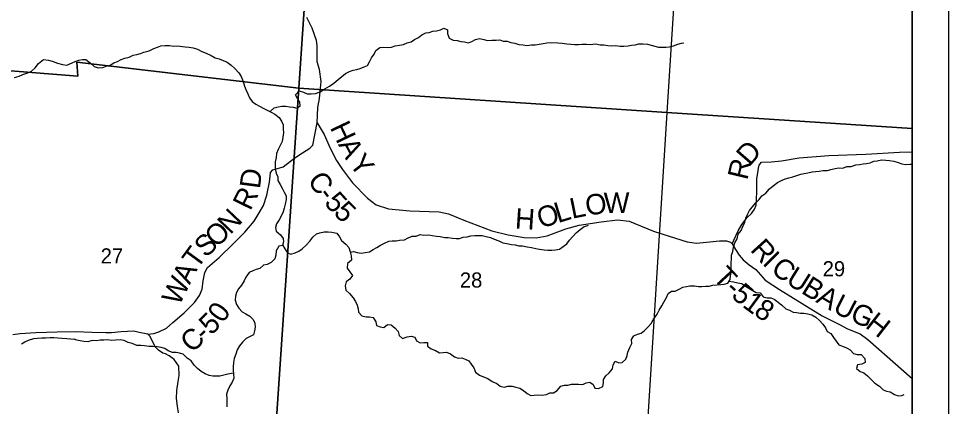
# Model space of a CAD drawing. Extents: x 0 to 34, y 0 to 22.
# Drawn here: x 28.342 to 30.917, y 17.138 to 18.211 of the extents above; entities that cross this region are included whole.
import ezdxf

# ---------------------------------------------------------------- set-up
doc = ezdxf.new("R2010")
doc.units = 0
for name, color, linetype in [('GM_X_County', 7, 'Continuous'), ('GM_X_County_Road', 7, 'Continuous'), ('GM_X_County_Road_Text', 7, 'Continuous'), ('GM_X_Minor_River', 7, 'Continuous'), ('GM_X_Section', 7, 'Continuous'), ('GM_X_Section_Text', 7, 'Continuous'), ('GM_X_State_Route', 7, 'Continuous'), ('GM_X_Township', 7, 'Continuous'), ('GM_X_Township_Road', 7, 'Continuous'), ('GM_X_Township_Road_Text', 7, 'Continuous'), ('SH_Data', 7, 'Continuous')]:
    doc.layers.add(name, color=color, linetype=linetype)

msp = doc.modelspace()

# ---------------------------------------------------------------- linework, layer by layer
at = {"layer": 'GM_X_County'}
msp.add_lwpolyline([(24.0167, 20.4902), (24.0167, 14.1), (30.8167, 14.1), (30.8167, 19.9966)], dxfattribs=at)
at = {"layer": 'GM_X_County_Road'}
for points in [[(29.1692, 17.9224), (29.1692, 17.9224), (29.1706, 17.9649), (29.1749, 17.9903), (29.1769, 18.0097), (29.1794, 18.0373), (29.1754, 18.07), (29.1691, 18.0917), (29.1692, 18.1065), (29.1686, 18.1368), (29.1671, 18.1501), (29.1552, 18.1847), (29.1406, 18.2141)], [(28.7, 17.3377), (28.7168, 17.3398), (28.7304, 17.3439), (28.7519, 17.354), (28.7694, 17.3695), (28.8003, 17.397), (28.8288, 17.4249), (28.8433, 17.4446), (28.8499, 17.462), (28.8527, 17.4847), (28.8581, 17.5082), (28.865, 17.5219), (28.8974, 17.5501), (28.9366, 17.5875), (28.9686, 17.6196), (28.9942, 17.6505), (29.0083, 17.6732), (29.0198, 17.6933), (29.029, 17.7224), (29.0364, 17.7581), (29.0384, 17.7748), (29.0393, 17.7854), (29.0461, 17.7922), (29.0526, 17.794), (29.0655, 17.7978), (29.0746, 17.8004), (29.1073, 17.8252), (29.1278, 17.8399), (29.1487, 17.8527), (29.1567, 17.861), (29.1692, 17.9224)], [(29.1692, 17.9224), (29.1884, 17.8904), (29.2052, 17.852), (29.2224, 17.8185), (29.2385, 17.7933), (29.2663, 17.7567), (29.3085, 17.714), (29.3323, 17.6953), (29.3667, 17.6848), (29.4257, 17.6792), (29.4787, 17.677), (29.5064, 17.6757), (29.5325, 17.6706), (29.5752, 17.6532), (29.6527, 17.624), (29.6981, 17.6123), (29.7419, 17.6052), (29.7756, 17.6043), (29.806, 17.6098), (29.8572, 17.6292), (29.8944, 17.6389), (29.9554, 17.6488), (30.0005, 17.6542), (30.0331, 17.6506), (30.1004, 17.6225), (30.1431, 17.609), (30.193, 17.5935), (30.2191, 17.5892), (30.2562, 17.5931), (30.2831, 17.596), (30.3025, 17.5959), (30.313, 17.5923), (30.3176, 17.5875)], [(30.3176, 17.5875), (30.3225, 17.5973), (30.3344, 17.6234), (30.3451, 17.6412), (30.3596, 17.6605), (30.3711, 17.6718), (30.3802, 17.6835), (30.3841, 17.6949), (30.3857, 17.7131), (30.3862, 17.7294), (30.3863, 17.7438), (30.3864, 17.7681), (30.3888, 17.7844), (30.3908, 17.7973), (30.3931, 17.8053), (30.3992, 17.814), (30.4268, 17.8146), (30.4545, 17.8171), (30.5034, 17.8259), (30.5856, 17.8319), (30.6876, 17.8359), (30.7808, 17.8414), (30.8167, 17.8418)]]:
    msp.add_lwpolyline(points, dxfattribs=at)
at = {"layer": 'GM_X_Minor_River'}
for points in [[(29.0384, 17.9535), (29.0497, 17.9641), (29.0611, 17.9668), (29.0706, 17.9685), (29.082, 17.969), (29.0918, 17.9665), (29.102, 17.9656), (29.1122, 17.9634), (29.1218, 17.9697), (29.1205, 17.9799), (29.1139, 17.9903), (29.1092, 17.9999), (29.1189, 18.0111), (29.1313, 18.007), (29.1415, 18.003), (29.1521, 18.0028), (29.1638, 18.0036), (29.1772, 18.0086), (29.1902, 18.0163), (29.2025, 18.0244), (29.2145, 18.0325), (29.2272, 18.0424), (29.2372, 18.0509), (29.2469, 18.0587), (29.258, 18.0645), (29.2687, 18.0681), (29.2782, 18.0705), (29.2877, 18.0726), (29.2988, 18.0776), (29.3083, 18.0816), (29.3135, 18.0913), (29.3194, 18.1026), (29.3268, 18.1123), (29.3312, 18.1228), (29.342, 18.1313), (29.3534, 18.1322), (29.3651, 18.1311), (29.3746, 18.1321), (29.3849, 18.1356), (29.3963, 18.1373), (29.4077, 18.1393), (29.4181, 18.1436), (29.4287, 18.1472), (29.4383, 18.1534), (29.4491, 18.1589), (29.4587, 18.1659), (29.4694, 18.1713), (29.4789, 18.173), (29.4889, 18.1766), (29.4991, 18.1775), (29.5101, 18.1803), (29.5197, 18.1842), (29.5295, 18.1798), (29.5296, 18.1696), (29.5346, 18.1573), (29.5451, 18.1514), (29.5564, 18.1504), (29.567, 18.1479), (29.5768, 18.1465), (29.5877, 18.1444), (29.5973, 18.1476), (29.6073, 18.1531), (29.6187, 18.1559), (29.6304, 18.1533), (29.6405, 18.1508), (29.6527, 18.1513), (29.664, 18.1518), (29.6743, 18.1523), (29.684, 18.1487), (29.695, 18.1485), (29.7052, 18.1448), (29.7161, 18.1431), (29.727, 18.139), (29.7395, 18.1384), (29.7493, 18.137), (29.7618, 18.1383), (29.772, 18.138), (29.7835, 18.1404), (29.7949, 18.1421), (29.8044, 18.1441), (29.8146, 18.1447), (29.8351, 18.1442), (29.8471, 18.1428), (29.8604, 18.141), (29.8713, 18.14), (29.8815, 18.139), (29.8921, 18.1395), (29.9024, 18.1405), (29.9145, 18.1402), (29.9247, 18.1392), (29.9391, 18.1415), (29.9523, 18.1386), (29.9629, 18.1383), (29.9739, 18.137), (29.9837, 18.136), (29.9951, 18.1365), (30.0075, 18.1347), (30.0178, 18.1352), (30.0295, 18.1361), (30.039, 18.1374), (30.0489, 18.1387)], [(28.4989, 18.0924), (28.5092, 18.0956), (28.5187, 18.0976), (28.5285, 18.0974), (28.5404, 18.0884), (28.5516, 18.0787), (28.5621, 18.075), (28.575, 18.0759), (28.5849, 18.0791), (28.5952, 18.0819), (28.606, 18.0885), (28.6155, 18.0924), (28.6262, 18.0983), (28.6365, 18.1011), (28.6484, 18.1042), (28.6591, 18.11), (28.6693, 18.1113), (28.6796, 18.1149), (28.6892, 18.1181), (28.7033, 18.1223), (28.7167, 18.1285), (28.7266, 18.1317), (28.7362, 18.1353), (28.7483, 18.1369), (28.7597, 18.1363), (28.7721, 18.1345), (28.782, 18.1354), (28.8031, 18.1326), (28.8148, 18.1316), (28.8254, 18.1299), (28.8371, 18.1266), (28.8498, 18.1202), (28.8611, 18.1154), (28.8749, 18.1087), (28.8862, 18.1027), (28.8971, 18.0998), (28.9087, 18.0954), (28.9192, 18.0906), (28.9304, 18.082), (28.9404, 18.0731), (28.9515, 18.0614), (28.9581, 18.0511), (28.9635, 18.0373), (28.9677, 18.0243), (28.9713, 18.0144), (28.9771, 18.0025), (28.981, 17.9921), (28.9887, 17.9813), (28.9988, 17.9739), (29.0089, 17.9691), (29.0209, 17.962), (29.0306, 17.9577), (29.0411, 17.9521), (29.0516, 17.9462), (29.0631, 17.9376), (29.0697, 17.9268), (29.0748, 17.9172), (29.0745, 17.9062), (29.0754, 17.8952), (29.0736, 17.8827), (29.0715, 17.8707), (29.0667, 17.8601), (29.0607, 17.8489), (29.0559, 17.8372), (29.0557, 17.8266), (29.0528, 17.8149), (29.0529, 17.8051), (29.0527, 17.7956), (29.0555, 17.783), (29.0594, 17.7734), (29.0596, 17.7628), (29.0662, 17.7521), (29.0731, 17.7401), (29.0774, 17.7302), (29.0825, 17.7202), (29.083, 17.71), (29.0805, 17.6975), (29.0776, 17.6862), (29.0747, 17.676), (29.0691, 17.6644), (29.0632, 17.6539), (29.0561, 17.6427), (29.0536, 17.6329), (29.0557, 17.623), (29.0668, 17.6121), (29.0749, 17.6024), (29.0751, 17.5929), (29.0726, 17.5831), (29.0627, 17.5807), (29.0556, 17.568), (29.0546, 17.5566), (29.0517, 17.546), (29.0416, 17.536), (29.0305, 17.5302), (29.0199, 17.5285), (29.0102, 17.5189), (28.9999, 17.5165), (28.9904, 17.5129), (28.9808, 17.5082), (28.971, 17.4951), (28.9662, 17.485)], [(30.0489, 18.1387), (30.0596, 18.1415), (30.0709, 18.1416), (30.0834, 18.1402), (30.0932, 18.1374), (30.1037, 18.1348), (30.1135, 18.132), (30.1237, 18.1317), (30.134, 18.1319), (30.1438, 18.1328), (30.1553, 18.1356), (30.1671, 18.1403), (30.1778, 18.1431), (30.1842, 18.1444)], [(28.331, 18.0478), (28.3432, 18.0514), (28.3539, 18.0562), (28.3676, 18.061), (28.3779, 18.0655), (28.3878, 18.0748), (28.3974, 18.0872), (28.4108, 18.0981), (28.4248, 18.0964), (28.4354, 18.0936), (28.4501, 18.0881), (28.4633, 18.0842), (28.4754, 18.0822), (28.4989, 18.0924)], [(30.6998, 17.8117), (30.7101, 17.8161), (30.7196, 17.8174), (30.7311, 17.8198), (30.7436, 17.8195), (30.7537, 17.8181), (30.7654, 17.816), (30.7771, 17.8123), (30.7876, 17.8086), (30.7982, 17.8073), (30.8096, 17.8078), (30.8167, 17.8082)], [(29.904, 17.1986), (29.9136, 17.2026), (29.9235, 17.2047), (29.9332, 17.198), (29.9379, 17.188), (29.9477, 17.1871), (29.9596, 17.1929), (29.962, 17.2027), (29.9619, 17.2121), (29.9678, 17.2219), (29.9774, 17.2304), (29.9864, 17.2412), (29.9885, 17.2525), (29.9941, 17.263), (30.0038, 17.2586), (30.0137, 17.2592), (30.0237, 17.268), (30.0274, 17.2782), (30.0291, 17.288), (30.0347, 17.3008), (30.0402, 17.3117), (30.039, 17.3223), (30.046, 17.3332), (30.056, 17.3379), (30.0655, 17.3399), (30.0751, 17.3473), (30.0848, 17.357), (30.0934, 17.367), (30.0993, 17.3771), (30.1098, 17.3928), (30.1162, 17.4044), (30.1232, 17.4157), (30.1284, 17.4262), (30.1359, 17.4389), (30.1403, 17.4502), (30.1503, 17.4564), (30.1597, 17.4566), (30.1716, 17.462), (30.1816, 17.4675), (30.1911, 17.4699), (30.2006, 17.4716), (30.2135, 17.4717), (30.2244, 17.4695), (30.2343, 17.4693), (30.2449, 17.4702), (30.2544, 17.4708), (30.2647, 17.4736), (30.276, 17.4741), (30.2863, 17.4754), (30.2958, 17.4763), (30.3057, 17.4787), (30.312, 17.4885), (30.3129, 17.4987), (30.3154, 17.5089), (30.315, 17.5221), (30.3149, 17.5347), (30.3159, 17.546), (30.3165, 17.5559), (30.3194, 17.5668), (30.3219, 17.5781), (30.3252, 17.5906), (30.3319, 17.6014), (30.3349, 17.6146), (30.343, 17.6247), (30.3478, 17.6356), (30.353, 17.6476), (30.3559, 17.6589), (30.3603, 17.6687), (30.3658, 17.6796), (30.3733, 17.6893), (30.3834, 17.7008), (30.393, 17.7101), (30.4001, 17.7201), (30.4113, 17.7282), (30.4213, 17.7394), (30.4318, 17.7483), (30.443, 17.7575), (30.4548, 17.7625), (30.4644, 17.7673), (30.4747, 17.7701), (30.4861, 17.7732), (30.4968, 17.7768), (30.5079, 17.7807), (30.5177, 17.782), (30.5273, 17.7841), (30.5391, 17.7869), (30.5493, 17.7874), (30.5588, 17.7883), (30.5694, 17.7907), (30.5816, 17.7908), (30.5915, 17.7933), (30.6029, 17.7964), (30.6135, 17.7977), (30.6241, 17.7975), (30.6356, 17.8018), (30.647, 17.8015), (30.6599, 17.8065), (30.6702, 17.8075), (30.6804, 17.8087), (30.6903, 17.8104), (30.6998, 17.8117)], [(29.2599, 17.5645), (29.2695, 17.5659), (29.2797, 17.5637), (29.2903, 17.562), (29.302, 17.5632), (29.3134, 17.5653), (29.3238, 17.5719), (29.3342, 17.5777), (29.3442, 17.5835), (29.3556, 17.5894), (29.3668, 17.5948), (29.3762, 17.5961), (29.3876, 17.5959), (29.3971, 17.5979), (29.4104, 17.5988), (29.4211, 17.6038), (29.4314, 17.6085), (29.4428, 17.609), (29.4543, 17.613), (29.4641, 17.6112), (29.477, 17.6121), (29.4868, 17.6103), (29.4992, 17.6085), (29.5098, 17.6079), (29.5219, 17.605), (29.5317, 17.6048), (29.5438, 17.603), (29.5536, 17.6024), (29.5631, 17.6026), (29.5726, 17.6058), (29.5844, 17.6066), (29.5947, 17.6098), (29.6057, 17.6111), (29.6156, 17.6105), (29.6258, 17.6103), (29.6371, 17.6081), (29.6491, 17.6048), (29.6589, 17.6001), (29.6716, 17.5956), (29.6833, 17.5904), (29.6935, 17.5883), (29.707, 17.5857), (29.7172, 17.5844), (29.7274, 17.5822), (29.7372, 17.582), (29.7504, 17.5794), (29.7618, 17.5777), (29.7742, 17.5751), (29.7848, 17.573), (29.7972, 17.5712), (29.8074, 17.5698), (29.8184, 17.57), (29.8283, 17.5709), (29.8401, 17.5729), (29.8504, 17.5803), (29.8601, 17.5873), (29.8675, 17.5977), (29.8768, 17.6081), (29.8858, 17.6182), (29.8969, 17.627), (29.9081, 17.6355), (29.9184, 17.6387), (29.9199, 17.6394)], [(29.073, 17.5846), (29.0788, 17.5735), (29.0862, 17.5631), (29.0959, 17.5587), (29.1074, 17.5623), (29.1177, 17.5677), (29.1273, 17.5736), (29.1385, 17.5843), (29.1482, 17.5947), (29.1568, 17.6059), (29.1669, 17.6152), (29.1764, 17.6184), (29.1878, 17.6208), (29.1996, 17.6205), (29.2098, 17.6199), (29.2233, 17.6169), (29.2307, 17.6065), (29.2365, 17.5969), (29.2477, 17.5868), (29.2565, 17.5771), (29.2597, 17.5653), (29.2628, 17.5539), (29.2637, 17.5428), (29.2525, 17.5329), (29.2518, 17.5204), (29.2592, 17.51), (29.2669, 17.5003), (29.2591, 17.4902), (29.2495, 17.4825), (29.2466, 17.4715), (29.2486, 17.459), (29.2582, 17.45), (29.2686, 17.4384), (29.2751, 17.4277), (29.2795, 17.4181), (29.2819, 17.4078), (29.2836, 17.3983), (29.2924, 17.3882), (29.3041, 17.3857), (29.314, 17.3858), (29.3242, 17.3837), (29.3311, 17.3718), (29.3331, 17.3619), (29.3436, 17.3575), (29.3534, 17.3558), (29.3635, 17.3643), (29.3741, 17.3633), (29.3845, 17.3543), (29.3926, 17.3447), (29.3954, 17.334), (29.405, 17.3254), (29.4176, 17.3297), (29.429, 17.3317), (29.4392, 17.3288), (29.4435, 17.3189), (29.4544, 17.3133), (29.4642, 17.3142), (29.4741, 17.3148), (29.4746, 17.3045), (29.4847, 17.2967), (29.4967, 17.2923), (29.5075, 17.286), (29.5174, 17.2865), (29.5273, 17.2878), (29.5382, 17.2834), (29.549, 17.2752), (29.5591, 17.2715), (29.569, 17.2721), (29.5787, 17.2681), (29.5885, 17.2637), (29.5951, 17.2541), (29.6028, 17.2444), (29.6075, 17.2325), (29.6183, 17.2243), (29.6291, 17.2195), (29.6415, 17.2147), (29.6535, 17.2061), (29.6662, 17.2005), (29.6759, 17.1935), (29.6864, 17.191), (29.6963, 17.1934), (29.7088, 17.1931), (29.719, 17.191), (29.7295, 17.1877), (29.74, 17.1818), (29.75, 17.1729), (29.7602, 17.1677), (29.77, 17.169), (29.781, 17.1695), (29.792, 17.1685), (29.8034, 17.1705), (29.8133, 17.1749), (29.8232, 17.175), (29.8336, 17.182), (29.8433, 17.1932), (29.8532, 17.1967), (29.8631, 17.1965), (29.8726, 17.1993), (29.8824, 17.1987), (29.8923, 17.1989), (29.904, 17.1986)], [(28.9662, 17.485), (28.9595, 17.4734), (28.9514, 17.4629), (28.9451, 17.4532), (28.9422, 17.4427), (28.942, 17.4317), (28.9455, 17.4198), (28.9521, 17.4098), (28.9609, 17.3994), (28.971, 17.3938), (28.9822, 17.3871), (28.9919, 17.3778), (28.9958, 17.3683), (28.9975, 17.3572), (28.9954, 17.347), (28.9924, 17.3357), (28.9817, 17.3303), (28.9721, 17.3255), (28.9621, 17.3155), (28.9539, 17.3051), (28.9472, 17.2946), (28.9435, 17.2818), (28.9387, 17.2698), (28.9373, 17.2588), (28.9359, 17.2475), (28.9361, 17.2376), (28.9374, 17.2266), (28.9382, 17.2156), (28.9331, 17.2043), (28.9268, 17.1942), (28.9216, 17.1825), (28.9176, 17.1713), (28.9188, 17.1595), (28.919, 17.1492), (28.9183, 17.1367)], [(30.3093, 17.4843), (30.3213, 17.4826), (30.3334, 17.48), (30.3447, 17.4775), (30.3547, 17.4701), (30.3644, 17.4645), (30.3749, 17.4586), (30.3846, 17.4531), (30.3956, 17.4517), (30.404, 17.4405), (30.415, 17.4384), (30.4248, 17.4382), (30.4346, 17.4345), (30.445, 17.426), (30.455, 17.4174), (30.4666, 17.4077), (30.4767, 17.4036), (30.4864, 17.3985), (30.4962, 17.3971), (30.5068, 17.3958), (30.5163, 17.3959), (30.5276, 17.3942), (30.5385, 17.3909), (30.5494, 17.3846), (30.5601, 17.3756), (30.5694, 17.3648), (30.576, 17.3552), (30.5814, 17.3452), (30.5912, 17.3396), (30.5989, 17.3281), (30.6062, 17.3181), (30.6132, 17.3081), (30.6233, 17.3044), (30.6342, 17.2996), (30.6447, 17.2941), (30.6539, 17.2836), (30.6641, 17.2811), (30.6754, 17.2809), (30.6854, 17.2697), (30.6863, 17.2594), (30.6767, 17.2543), (30.6653, 17.253), (30.6624, 17.2421), (30.6725, 17.2339), (30.6823, 17.2307), (30.6931, 17.2221), (30.7031, 17.2124), (30.713, 17.2015), (30.7258, 17.194), (30.7357, 17.1832), (30.7455, 17.18), (30.7557, 17.1778), (30.7676, 17.1707), (30.7774, 17.1664), (30.7876, 17.1673), (30.7942, 17.1705)], [(28.3499, 17.3105), (28.3595, 17.3161), (28.369, 17.3213), (28.3842, 17.3253), (28.3945, 17.3264), (28.4062, 17.3274), (28.4168, 17.3276), (28.429, 17.3282), (28.4396, 17.3281), (28.4506, 17.3272), (28.4619, 17.3263), (28.4752, 17.3254), (28.4858, 17.3245), (28.4956, 17.3233)], [(28.9371, 17.2291), (28.9214, 17.2265), (28.9104, 17.2238), (28.8994, 17.2217), (28.8895, 17.2208), (28.8797, 17.221), (28.8695, 17.2235), (28.8582, 17.2276), (28.8478, 17.2343), (28.8377, 17.2424), (28.8281, 17.2521), (28.82, 17.2633), (28.8092, 17.2711), (28.7977, 17.2824), (28.7879, 17.2853), (28.7781, 17.2866), (28.7679, 17.2865), (28.7566, 17.2917), (28.7469, 17.2979), (28.7371, 17.3004), (28.7258, 17.3022), (28.7137, 17.3032), (28.7035, 17.3038), (28.6903, 17.3053), (28.6805, 17.3062), (28.6691, 17.3057), (28.6567, 17.3113), (28.6458, 17.3146), (28.6342, 17.3202), (28.6236, 17.3215), (28.6107, 17.3207), (28.5997, 17.3202), (28.5888, 17.3219), (28.5785, 17.321), (28.5683, 17.3205), (28.5573, 17.3188), (28.5459, 17.3198), (28.5334, 17.3167), (28.5224, 17.317), (28.5126, 17.3187), (28.503, 17.3213), (28.4956, 17.3233)]]:
    msp.add_lwpolyline(points, dxfattribs=at)
at = {"layer": 'GM_X_Section'}
for p, q in [((30.8167, 17.9065), (30.8167, 18.9061)), ((30.8167, 16.9208), (30.8167, 17.9065))]:
    msp.add_line(p, q, dxfattribs=at)
for points in [[(29.5042, 18.9967), (30.2006, 18.9496), (30.1374, 17.9516), (29.1178, 18.0184), (29.1658, 18.7281)], [(29.1658, 18.7281), (29.1178, 18.0184), (28.5033, 18.0906), (28.5064, 18.0521), (28.157, 18.0791), (28.1647, 18.1688), (28.1804, 18.1807), (28.214, 18.1975), (28.5041, 18.3264), (28.8554, 18.5398)], [(28.157, 18.0791), (28.5064, 18.0521), (28.5033, 18.0906), (29.1178, 18.0184), (29.0528, 17.0493), (28.8721, 17.0617), (28.0732, 17.1088)], [(29.1178, 18.0184), (30.1374, 17.9516), (30.0764, 16.9749), (29.8965, 16.988), (29.0528, 17.0493)]]:
    msp.add_lwpolyline(points, close=True, dxfattribs=at)
for points in [[(30.8167, 18.9061), (30.2006, 18.9496), (30.1374, 17.9516), (30.8167, 17.9065)], [(30.8167, 17.9065), (30.1374, 17.9516), (30.0764, 16.9749), (30.8167, 16.9208)]]:
    msp.add_lwpolyline(points, dxfattribs=at)
at = {"layer": 'GM_X_State_Route'}
msp.add_lwpolyline([(28.7852, 17.1202), (28.782, 17.1379), (28.7793, 17.159), (28.7804, 17.1816), (28.7841, 17.2068), (28.7863, 17.2234), (28.7857, 17.2485), (28.7729, 17.2676), (28.7594, 17.2779), (28.7485, 17.2827), (28.7415, 17.285), (28.7294, 17.2933), (28.7251, 17.2978), (28.7206, 17.3021), (28.712, 17.3197), (28.7058, 17.332), (28.7, 17.3377), (28.6758, 17.3423), (28.661, 17.3461), (28.6259, 17.3438), (28.5996, 17.3411), (28.5836, 17.3411), (28.5452, 17.3421), (28.4999, 17.3441), (28.4488, 17.3426), (28.3893, 17.3413), (28.3461, 17.338), (28.326, 17.3355)], dxfattribs=at)
at = {"layer": 'GM_X_Township'}
msp.add_lwpolyline([(27.704, 14.1), (30.8167, 14.1), (30.8167, 19.9966)], dxfattribs=at)
at = {"layer": 'GM_X_Township_Road'}
msp.add_lwpolyline([(30.3176, 17.5875), (30.3269, 17.5719), (30.3371, 17.5566), (30.348, 17.5433), (30.3653, 17.5299), (30.3834, 17.5161), (30.4094, 17.4871), (30.449, 17.4615), (30.5113, 17.422), (30.5668, 17.3887), (30.6151, 17.3645), (30.6377, 17.3519), (30.6725, 17.3387), (30.694, 17.3231), (30.8167, 17.2149)], dxfattribs=at)
at = {"layer": 'SH_Data'}
for points in [[(23.9167, 21), (30.9167, 21), (30.9167, 14), (23.9167, 14)], [(24.0167, 20.9), (30.8167, 20.9), (30.8167, 14.1), (24.0167, 14.1)]]:
    msp.add_lwpolyline(points, close=True, dxfattribs=at)

# ---------------------------------------------------------------- texts
at = {"layer": 'GM_X_County_Road_Text'}
for s, rotation, p in [('H', 295.3985, (29.2034, 17.9099)), ('A', 297.6051, (29.2259, 17.8626)), ('Y', 307.8741, (29.255, 17.809)), ('D', 49.0652, (30.3671, 17.8012)), ('R', 76.6804, (30.3596, 17.7621)), ('D', 82.5473, (29.01, 17.7382)), ('C', 304.6969, (29.1402, 17.7631)), ('R', 63.7158, (28.9835, 17.677)), ('-', 307.0538, (29.1683, 17.7227)), ('5', 312.2006, (29.1859, 17.6998)), ('L', 11.4158, (29.8745, 17.6567)), ('O', 8.5664, (29.9155, 17.665)), ('W', 1.1399, (29.963, 17.6723)), ('5', 315.2829, (29.2117, 17.6714)), ('O', 17.4583, (29.7878, 17.6296)), ('L', 17.0687, (29.8354, 17.6446)), ('N', 46.5101, (28.9282, 17.6113)), ('H', 356.4168, (29.7154, 17.63)), ('O', 44.1787, (28.8905, 17.5747)), ('S', 41.497, (28.8597, 17.5473)), ('T', 53.8107, (28.8368, 17.5154)), ('A', 63.5327, (28.8158, 17.4728)), ('W', 64.082, (28.7871, 17.4137)), ('0', 55.1677, (28.9077, 17.3658)), ('5', 44.7363, (28.8755, 17.3326)), ('C', 41.7308, (28.8211, 17.2835)), ('-', 42.5328, (28.8566, 17.3151))]:
    msp.add_text(s, height=0.0568, rotation=rotation, dxfattribs=at).set_placement(p)
at = {"layer": 'GM_X_Section_Text'}
for s, p in [('27', (28.5693, 17.5332)), ('29', (30.5685, 17.4977)), ('28', (29.5639, 17.4665))]:
    msp.add_text(s, height=0.04186, rotation=0, dxfattribs=at).set_placement(p)
at = {"layer": 'GM_X_Township_Road_Text'}
for s, rotation, p in [('R', 312.2585, (30.3657, 17.5695)), ('I', 315.6177, (30.3996, 17.5324)), ('C', 322.7381, (30.4221, 17.511)), ('T', 312.848, (30.2624, 17.4927)), ('U', 327.9213, (30.4638, 17.4796)), ('B', 327.9733, (30.5063, 17.453)), ('-', 318.0771, (30.2954, 17.4576)), ('5', 318.2813, (30.3129, 17.4419)), ('A', 329.5017, (30.5472, 17.4274)), ('1', 323.6824, (30.3436, 17.4149)), ('8', 327.4755, (30.3751, 17.3919)), ('U', 332.9778, (30.5936, 17.4002)), ('G', 336.1002, (30.6412, 17.376)), ('H', 322.2499, (30.6838, 17.3576))]:
    msp.add_text(s, height=0.0568, rotation=rotation, dxfattribs=at).set_placement(p)

doc.saveas('drawing.dxf')
